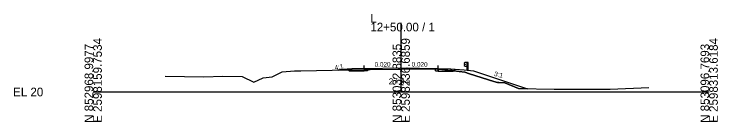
# Model space of a CAD drawing. Extents: x -26 to 1203, y -10 to 9526.
# Drawn here: x -25.7 to 202.8, y 2490.3 to 2525.2 of the extents above; entities that cross this region are included whole.
import ezdxf

# ---------------------------------------------------------------- set-up
doc = ezdxf.new("R2010")
doc.units = 0
for name, color, linetype in [('Exist Cross Section Cell', 7, 'Continuous'), ('Exist XS Center Line Elevation Label', 7, 'Continuous'), ('Exist XS Ground Line', 7, 'Continuous'), ('Prop XS Earthwork Shape', 7, 'Continuous'), ('Prop XS EOT Tick Mark', 7, 'Continuous'), ('Prop XS Finish Grade', 7, 'Continuous'), ('Prop XS Finish Grade Earthwork', 7, 'Continuous'), ('Prop XS Finish Grade Paved Shoulder', 7, 'Continuous'), ('Prop XS Finish Grade Pavement', 7, 'Continuous'), ('Prop XS Guardrail', 7, 'Continuous'), ('Prop XS Pvmt Edge Slope', 7, 'Continuous'), ('Prop XS SE Text', 7, 'Continuous'), ('Prop XS Side Slope Text', 7, 'Continuous'), ('Prop XS Subgrade Earthwork', 7, 'Continuous')]:
    doc.layers.add(name, color=color, linetype=linetype)

msp = doc.modelspace()

# ---------------------------------------------------------------- linework, layer by layer
at = {"layer": 'Exist Cross Section Cell'}
for p, q in [((100, 2500), (100, 2522.45)), ((0, 2500), (100, 2500)), ((100, 2500), (200, 2500))]:
    msp.add_line(p, q, dxfattribs=at)
at = {"layer": 'Exist XS Ground Line'}
for p, q in [((67.38, 2506.85), (77.63, 2507.04)), ((77.63, 2507.04), (87.88, 2507.24)), ((87.88, 2507.24), (89.88, 2507.28)), ((89.88, 2507.28), (100.04, 2507.44)), ((100.04, 2507.44), (107.72, 2507.48)), ((107.72, 2507.48), (111.14, 2507.48)), ((111.14, 2507.48), (115.1, 2507.1)), ((115.1, 2507.1), (120.71, 2506.48)), ((23.38, 2505.14), (35.95, 2504.91)), ((35.95, 2504.91), (42.09, 2505.16)), ((42.09, 2505.16), (48.38, 2505.05)), ((48.38, 2505.05), (52.18, 2503.15)), ((55.16, 2504.64), (58.16, 2504.89)), ((58.16, 2504.89), (61.38, 2506.5)), ((61.38, 2506.5), (65.38, 2506.81)), ((65.38, 2506.81), (67.38, 2506.85)), ((120.71, 2506.48), (122.16, 2505.88)), ((122.16, 2505.88), (130.12, 2503.43)), ((52.18, 2503.15), (55.16, 2504.64)), ((130.12, 2503.43), (131.23, 2503.07)), ((131.23, 2503.07), (131.7, 2503.05)), ((131.7, 2503.05), (133.66, 2502.94)), ((133.66, 2502.94), (138.14, 2501.1)), ((138.14, 2501.1), (149.71, 2500.87)), ((149.71, 2500.87), (167.86, 2500.92)), ((167.86, 2500.92), (180.4, 2501.42))]:
    msp.add_line(p, q, dxfattribs=at)
at = {"layer": 'Prop XS Earthwork Shape'}
for points in [[(79.59, 2507.08), (82.75, 2507.14), (82.5, 2507.38), (80, 2507.18)], [(82.75, 2507.14), (87.88, 2507.24), (89.03, 2507.26), (89.03, 2506.81), (88, 2506.79), (83.19, 2506.7)], [(111.14, 2506.81), (111.14, 2507.47), (112, 2507.39), (112, 2506.8)], [(116.81, 2506.7), (117, 2506.89), (115.1, 2507.1), (112, 2507.39), (112, 2506.8)], [(123.46, 2506.91), (141.04, 2501.04), (138.14, 2501.1), (133.66, 2502.94), (131.7, 2503.05), (131.23, 2503.07), (130.12, 2503.43), (122.16, 2505.88), (120.71, 2506.48), (117, 2506.89), (117.5, 2507.38), (120.46, 2507.15)]]:
    msp.add_lwpolyline(points, close=True, dxfattribs=at)
at = {"layer": 'Prop XS EOT Tick Mark'}
for p, q in [((88, 2507.58), (88, 2508.58)), ((112, 2507.58), (112, 2508.58))]:
    msp.add_line(p, q, dxfattribs=at)
at = {"layer": 'Prop XS Finish Grade'}
for p, q in [((84, 2507.5), (82.5, 2507.38)), ((116, 2507.5), (117.5, 2507.38))]:
    msp.add_line(p, q, dxfattribs=at)
at = {"layer": 'Prop XS Finish Grade Earthwork'}
for p, q in [((80, 2507.18), (79.59, 2507.08)), ((82.5, 2507.38), (80, 2507.18)), ((117.5, 2507.38), (120.46, 2507.15)), ((120.46, 2507.15), (123.46, 2506.91)), ((123.46, 2506.91), (141.04, 2501.04))]:
    msp.add_line(p, q, dxfattribs=at)
at = {"layer": 'Prop XS Finish Grade Paved Shoulder'}
for p, q in [((88, 2507.58), (84, 2507.5)), ((112, 2507.58), (116, 2507.5))]:
    msp.add_line(p, q, dxfattribs=at)
at = {"layer": 'Prop XS Finish Grade Pavement'}
for p, q in [((88, 2507.58), (100, 2507.82)), ((100, 2507.82), (112, 2507.58))]:
    msp.add_line(p, q, dxfattribs=at)
at = {"layer": 'Prop XS Guardrail'}
for p, q in [((120.49, 2509.34), (120.46, 2509.28)), ((120.78, 2509.54), (120.49, 2509.34)), ((121.28, 2509.54), (120.78, 2509.54)), ((121.78, 2509.54), (121.28, 2509.54)), ((121.28, 2509.54), (121.28, 2507.04)), ((121.78, 2507.04), (121.78, 2509.54)), ((120.46, 2509.28), (120.49, 2509.22)), ((120.49, 2508.73), (120.46, 2508.67)), ((120.46, 2508.67), (120.49, 2508.61)), ((120.49, 2509.22), (120.78, 2509.02)), ((120.78, 2508.93), (120.49, 2508.73)), ((120.49, 2508.61), (120.78, 2508.41)), ((120.78, 2509.02), (120.78, 2508.93)), ((120.78, 2508.41), (121.28, 2508.41))]:
    msp.add_line(p, q, dxfattribs=at)
at = {"layer": 'Prop XS Pvmt Edge Slope'}
for p, q in [((84, 2507.5), (83.19, 2506.7)), ((116, 2507.5), (116.81, 2506.7))]:
    msp.add_line(p, q, dxfattribs=at)
at = {"layer": 'Prop XS Subgrade Earthwork'}
for p, q in [((83.19, 2506.7), (82.5, 2507.38)), ((89.03, 2506.81), (89.03, 2507.26)), ((111.14, 2506.81), (111.14, 2507.47)), ((112, 2506.8), (112, 2507.39)), ((116.81, 2506.7), (117.5, 2507.38)), ((88, 2506.79), (83.19, 2506.7)), ((89.03, 2506.81), (88, 2506.79)), ((111.14, 2506.81), (112, 2506.79)), ((112, 2506.79), (116.81, 2506.7))]:
    msp.add_line(p, q, dxfattribs=at)

# ---------------------------------------------------------------- texts
at = {"layer": 'Exist Cross Section Cell'}
for s, p in [('L', (90, 2522.45)), ('12+50.00 / 1', (90, 2519.65)), ('EL 20', (-26, 2498.6))]:
    msp.add_text(s, height=2.8, dxfattribs=at).set_placement(p)
for s, p in [('E 2598159.7534', (2.8, 2490)), ('E 2598236.6859', (102.8, 2490)), ('E 2598313.6184', (202.8, 2490)), ('N 852968.9977', (0, 2490)), ('N 853032.8835', (100, 2490)), ('N 853096.7693', (200, 2490))]:
    msp.add_text(s, height=2.8, rotation=90, dxfattribs=at).set_placement(p)
at = {"layer": 'Exist XS Center Line Elevation Label'}
msp.add_text('27.44', height=2, dxfattribs=at).set_placement((95.93, 2502.44))
at = {"layer": 'Prop XS SE Text'}
for rotation, p in [(1.1458, (91.38, 2508.15)), (358.8542, (103.38, 2508.26))]:
    msp.add_text('0.020', height=1.5, rotation=rotation, dxfattribs=at).set_placement(p)
at = {"layer": 'Prop XS Side Slope Text'}
for s, rotation, p in [('4:1', 13.2903, (78.57, 2507.06)), ('3:1', 345.9638, (130.07, 2505.25))]:
    msp.add_text(s, height=1.5, rotation=rotation, dxfattribs=at).set_placement(p)

doc.saveas('drawing.dxf')
